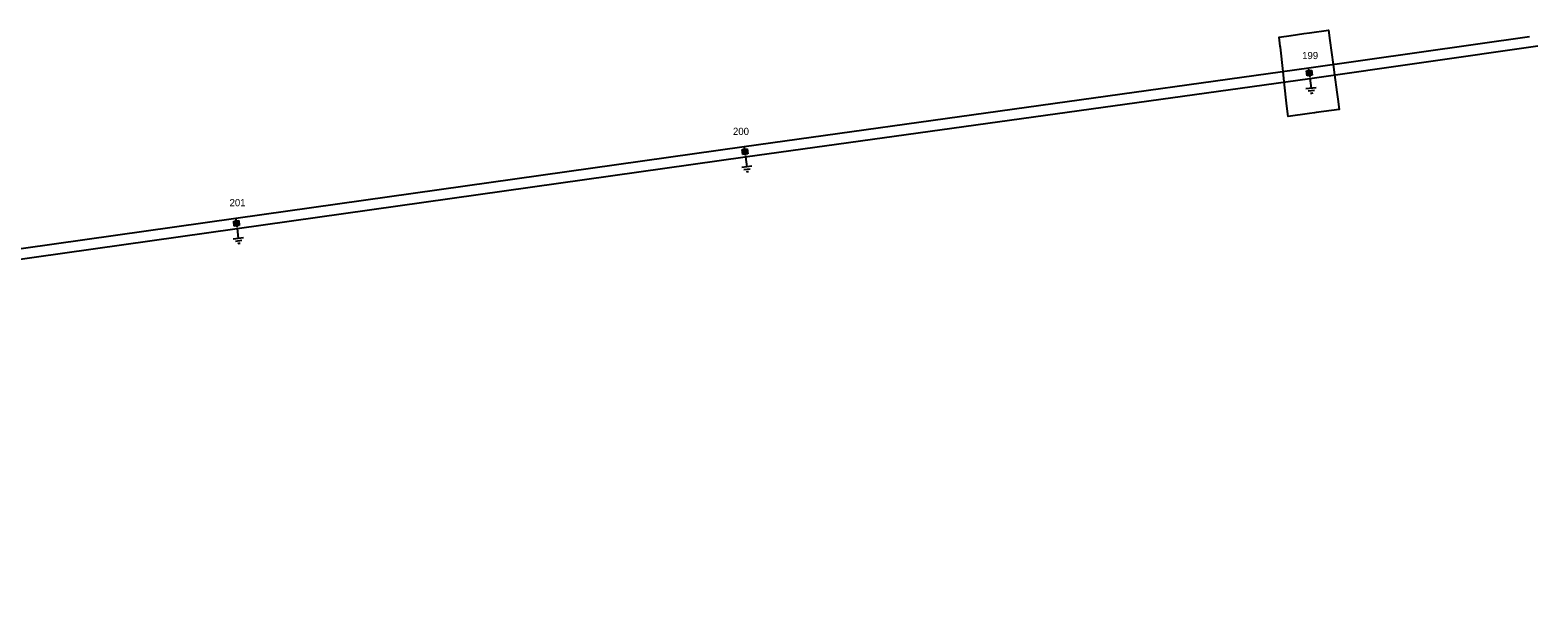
# Model space of a CAD drawing. Extents: x -545588 to -543214, y -1196037 to -1194452.
# Drawn here: x -544449.4 to -544081.8, y -1194901.6 to -1194765.7 of the extents above; entities that cross this region are included whole.
import ezdxf

# ---------------------------------------------------------------- set-up
doc = ezdxf.new("R2010")
doc.units = 0
for name, color, linetype in [('Vrstva 1', 7, 'Continuous'), ('Vrstva 13', 7, 'Continuous'), ('Vrstva 14', 7, 'Continuous'), ('Vrstva 15', 7, 'Continuous'), ('Vrstva 2', 7, 'Continuous'), ('Vrstva 35', 7, 'Continuous')]:
    doc.layers.add(name, color=color, linetype=linetype)

# ---------------------------------------------------------------- blocks, each defined once
blk = doc.blocks.new('VN810')
at = {"layer": 'Vrstva 14'}
for points in [[(0, -1.25), (0, -3.75)], [(1.25, -3.75), (-1.25, -3.75)], [(0.77, -4.37), (-0.8, -4.37)], [(0, -5), (-0.25, -5)], [(0.27, -5), (0, -5)]]:
    blk.add_lwpolyline(points, dxfattribs=at)
blk = doc.blocks.new('VN470')
at = {"layer": 'Vrstva 2'}
for points in [[(-1.23, 1.22), (1.23, 1.22)], [(-1.23, -1.23), (-1.23, 1.22)], [(-0.92, 0.9), (0.92, 0.9)], [(-0.92, -0.95), (-0.92, 0.9)], [(-0.61, 0.61), (0.61, 0.61)], [(-0.61, -0.62), (-0.61, 0.61)], [(-0.31, -0.27), (-0.31, 0.34)], [(-0.31, 0.34), (0.31, 0.34)], [(0, 1.22), (0, 1.97)], [(0.31, 0.34), (0.31, -0.27)], [(0.61, 0.61), (0.61, -0.62)], [(0.92, 0.9), (0.92, -0.95)], [(1.23, 1.22), (1.23, -1.23)], [(1.23, -1.23), (-1.23, -1.23)], [(0.92, -0.95), (-0.92, -0.95)], [(0.61, -0.62), (-0.61, -0.62)], [(0.31, -0.27), (-0.31, -0.27)], [(0, -1.23), (0, -1.98)]]:
    blk.add_lwpolyline(points, dxfattribs=at)

msp = doc.modelspace()

# ---------------------------------------------------------------- linework, layer by layer
at = {"layer": 'Vrstva 1'}
for points in [[(-544083.88, -1194767.33), (-544137.68, -1194774.97), (-544275.32, -1194794.17), (-544399.3, -1194811.66), (-544539.71, -1194831.51), (-544666.5, -1194849.29), (-544797.03, -1194867.27), (-544922.4, -1194884.94), (-545023.84, -1194899.15), (-545076.32, -1194876.08), (-545112.71, -1194859.53)], [(-545068.12, -1194888.96), (-545023.6, -1194901.6), (-544922.06, -1194887.4), (-544796.64, -1194869.77), (-544666.32, -1194851.78), (-544539.47, -1194833.99), (-544398.96, -1194814.1), (-544275.11, -1194796.62), (-544137.43, -1194777.48), (-544081.81, -1194769.58)]]:
    msp.add_lwpolyline(points, dxfattribs=at)
at = {"layer": 'Vrstva 35'}
msp.add_lwpolyline([(-544144.59, -1194769.89), (-544144.62, -1194769.62), (-544144.87, -1194767.39), (-544141.99, -1194766.99), (-544138.86, -1194766.56), (-544137.5, -1194766.37), (-544132.87, -1194765.71), (-544132.53, -1194768.2), (-544131.72, -1194774.13), (-544131.38, -1194776.62), (-544130.81, -1194780.81), (-544130.57, -1194782.55), (-544130.23, -1194785.04), (-544135.84, -1194785.84), (-544136.25, -1194785.9), (-544137.5, -1194786.07), (-544142.7, -1194786.79), (-544142.98, -1194784.3), (-544143.65, -1194778.34), (-544143.92, -1194775.84)], close=True, dxfattribs=at)

# ---------------------------------------------------------------- block references
at = {"layer": 'Vrstva 13'}
for p, xscale, yscale, rotation in [((-544137.55, -1194776.18), 0.49999999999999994, 0.4999999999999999, 6.796644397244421), ((-544275.14, -1194795.36), 0.49999999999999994, 0.4999999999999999, 6.796644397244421), ((-544399.12, -1194812.84), 0.5, 0.5000000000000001, 6.796644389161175)]:
    msp.add_blockref('VN470', p, dxfattribs=dict(at, xscale=xscale, yscale=yscale, rotation=rotation))
at = {"layer": 'Vrstva 15', "rotation": 6.796644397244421}
for p in [(-544137.55, -1194776.18), (-544275.14, -1194795.36), (-544399.12, -1194812.84)]:
    msp.add_blockref('VN810', p, dxfattribs=at)

# ---------------------------------------------------------------- texts
at = {"layer": 'Vrstva 14'}
for s, p in [('199', (-544139.28, -1194772.78)), ('200', (-544278.06, -1194791.29)), ('201', (-544400.81, -1194808.69))]:
    msp.add_text(s, height=1.75, dxfattribs=at).set_placement(p)

doc.saveas('drawing.dxf')
